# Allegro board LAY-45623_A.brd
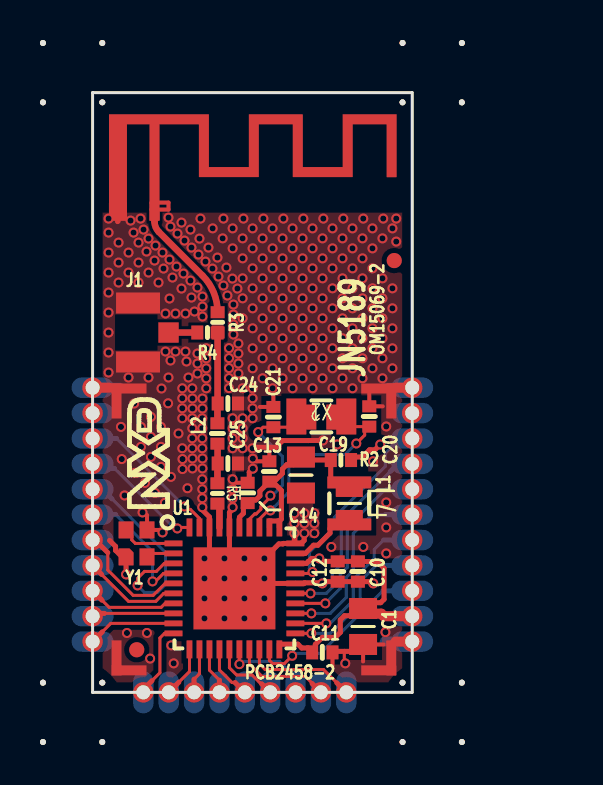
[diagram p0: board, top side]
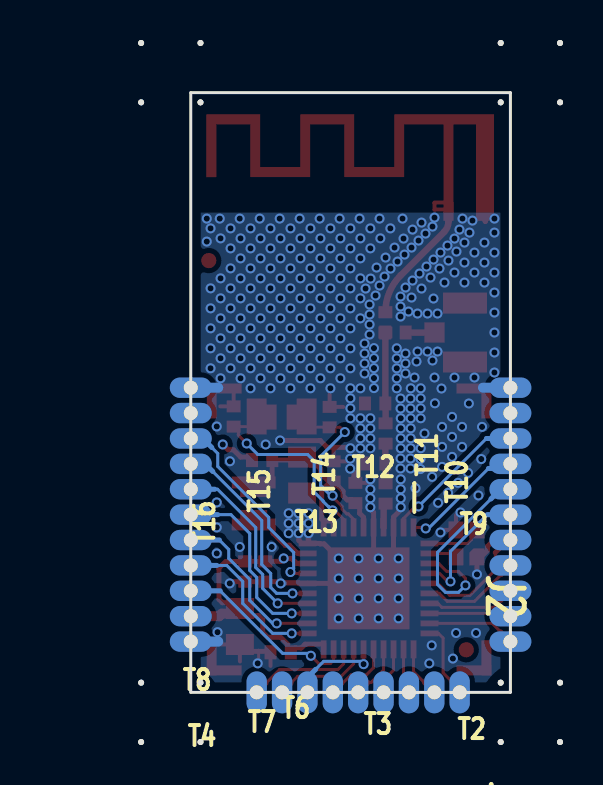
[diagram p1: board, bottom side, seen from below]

Outline 16 x 30 mm; copper layers: TOP, ANALOGUE GROUND, DIGITAL GROUND, BOTTOM. Coordinates in mm from the lower left corner of the outline.
Outline path: 0,30 16,30 16,0 0,0 0,30

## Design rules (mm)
net group ALIM: nets N16830755 N16830789 VDD
net group DEFAUT: nets LA LB N16830681 N16830775 N16832469 N16842652 PIO_0/SPI1_SCK PIO_1/SPI1_MISO PIO_2/SPI1_MOSI PIO_3/SPI1_SSELN0 PIO_4/PWM4-PU PIO_5/ISP_ENTRY PIO_6/PWM6-PD PIO_7/PWM7-PD PIO_8/USART0_TXD PIO_9/USART0_RXD PIO_10/I2C0_SCL PIO_11/I2C0_SDA PIO_12/SWCLK PIO_13/SWDIO PIO_14/ADC0 PIO_15/ADC1 PIO_16/SPIFI_CSN PIO_17/SPIFI_IO3 PIO_18/SPIFI_CLK PIO_19/SPIFI_IO0 PIO_20/SPIFI_IO2 PIO_21_SPIFI_IO1 RSTN
net group Z50: nets N16830709 N16830719 N16830729 N16849423 N16850832

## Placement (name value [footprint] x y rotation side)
1  BUBBLE-01  [BUBBLE_DIAM8]  23.55 23.95 0 top
ANT1  NC  [PCB_ANT_APPS]  3.1 23.85 0 top
C1  10uF  [C0805]  13.54 3.29 90 top
C10  100nF  [C0402]  13.28 6.04 90 top
C11  100nF  [C0402]  11.5 2 0 top
C12  47pF  [C0402]  12.27 6.04 90 top
C13  100nF  [C0402]  8.85 11.05 90 top
C14  47pF  [C0402]  7.76 9.97 90 top
C19  10uF  [C0805]  10.43 10.87 270 top
C20  NC  [C0402]  13.85 13.8 270 top
C21  NC  [C0402]  9.05 13.77 90 top
C24  0.8pF  [C0402]  6.77 14.45 180 top
C25  2.0pF  [C0402]  6.77 11.45 180 top
FID1  NC  [FID1]  2.21 2.13 0 top
FID2  NC  [FID1]  15.1 21.6 0 top
J1  SMC_UFL  [SMC-UFL-R-SMT]  2.27 18 270 top
L1  4,7uH_NC  [IND_CB_2518_2520]  12.85 9.45 270 top
L2  2.9nH  [SELF_0402]  6.25 12.95 270 top
L4  4.7uH  [0805C_IPCC]  12.85 9.45 270 top
LY1  NC  [LYRE_31PTS_CARRIER]  0 12.7 0 top
NOREF  -  []  16 0 90 top
NOREF#2  -  []  2.8 11.95 90 top
NOREF#3  -  [unnamed#2]  17 -1 0 top
NOREF#4  -  []  0 30 0 top
NOREF#5  -  [unnamed#2]  -1 31 0 top
NOREF#6  -  [unnamed#2]  17 31 0 top
NOREF#7  -  []  0 0 0 top
NOREF#8  -  [unnamed#2]  -1 -1 0 top
NOREF#9  -  []  0 0 90 top
NOREF#10  -  []  62.65 28.15 0 top
NOREF#11  -  []  16.52 -165.47 0 top
NOREF#12  -  []  -76.6 -194.1 0 top
R2  NC  [R0402]  12.43 11.62 0 top
R3  0R  [R0402]  6.26 18.51 270 top
R4  NC  [R0402]  5.75 18 180 top
R5  0R  [R0402]  6.25 9.95 270 top
SH1  SHIELD-13.7X14.1  [SHIELD_13MM7X14MM1]  1.2 1.1 0 top
U1  JN5189_40  [SOT618-1_HVQFN40_050_JN518X]  7.1 5.2 0 top
X1  32.768Khz_NC  [NX3215SA]  11.45 13.8 180 top
X2  32.768Khz  [NX2012SA]  11.45 13.77 180 top
Y1  32.000Mhz  [NX2016SA]  2.2 7.45 270 top

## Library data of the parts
1 = BUBBLE: alternate symbols: (BUBBLE_DIAM4)
ANT1 = ANTENNA_JN518x: alternate symbols: (pcb_ant_apps_flip)
C1 C19 = CAPA: alternate symbols: (0805C); tolerance: 10%
C10-C14 = CAPA: User Part Number: BCNNUMBER; Tolerance: 5%; alternate symbols: (0402C); tolerance: 5%
C20 C21 = CAPA: User Part Number: BCNNUMBER; Tolerance: -; alternate symbols: (0402C); tolerance: -
C24 C25 = CAPA: User Part Number: BCNNUMBER; Tolerance: +/-0.1pF; alternate symbols: (0402C); tolerance: +/-0.1pF
FID1 FID2 = MIRE
J1 = SMC_UFL
L1 = SELF: Tolerance: TOLERANCE; User Part Number: PARTNUM
L2 = SELF: Tolerance: TOLERANCE; User Part Number: BCNNUMBER
L4 = SELF
LY1 = LYRE_MODJN518x_31PTS
R2 R4 = RES: User Part Number: BCNNUMBER; Tolerance: -; tolerance: -
R3 R5 = RES: User Part Number: BCNNUMBER; Tolerance: -; alternate symbols: (0402R); tolerance: -
SH1 = SHIELD_8PTS
U1 = JN518x_QFN40: Tolerance: TOL; User Part Number: PN
X1 X2 = XTAL
Y1 = XTAL_NX2016_4P

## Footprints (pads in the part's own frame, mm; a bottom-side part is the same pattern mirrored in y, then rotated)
0805C_IPCC
  rect 0.95x1.35 smd: 1(-0.8,0) 2(0.8,0)
BUBBLE_DIAM8
  round 0 smd: 1(0,0)
C0402
  rect 0.6x0.7 smd: 1(-0.508,0) 2(0.508,0)
C0805
  rect 1.05x1.4 smd: 1(-0.9,0) 2(0.9,0)
FID1
  round 0.76 smd: 1(0,0)
IND_CB_2518_2520
  rect 0.6x2.2 smd: 1(-1.05,0) 2(1.05,0)
LYRE_31PTS_CARRIER
  round 1.02 hole 0.7: 1(0,2.54) 2(0,1.27) 3(0,0) 4(0,-1.27) 5(0,-2.54) 6(0,-3.81) 7(0,-5.08) 8(0,-6.35) 9(0,-7.62) 10(0,-8.89) 11(0,-10.16) 12(2.54,-12.7) 13(3.81,-12.7) 14(5.08,-12.7) 15(6.35,-12.7) 16(7.62,-12.7) 17(8.89,-12.7) 18(10.16,-12.7) 19(11.43,-12.7) 20(12.7,-12.7) 21(16,-10.16) 22(16,-8.89) 23(16,-7.62) 24(16,-6.35) 25(16,-5.08) 26(16,-3.81) 27(16,-2.54) 28(16,-1.27) 29(16,0) 30(16,1.27) 31(16,2.54)
NX2012SA
  rect 1x1.25 smd: 1(-0.75,0) 2(0.75,0)
NX2016SA
  rect 0.85x0.75 smd: 1(-0.675,-0.525) 3(0.675,0.525) 4(-0.675,0.525)
  custom 0.188x0.188 smd: 2(0.675,-0.525)
NX3215SA
  rect 1x1.8 smd: 1(-1.25,0) 2(1.25,0)
PCB_ANT_APPS
  rect 0.9x0.9 smd: 1(-1.829,0.2)
  rect 0.5x0.5 smd: 3(0,0)
R0402
  rect 0.6x0.7 smd: 1(-0.508,0) 2(0.508,0)
SELF_0402
  rect 0.6x0.7 smd: 1(-0.508,0) 2(0.508,0)
SHIELD_13MM7X14MM1
  rect 0.5x1.75 smd: 1(0,0.625) 4(13.75,0.625) 5(13.75,13.475) 8(0,13.475)
  rect 1.75x0.5 smd: 2(0.625,0) 3(13.125,0) 6(13.125,14.1) 7(0.625,14.1)
SMC-UFL-R-SMT
  rect 1.016x1.016 smd: 1(0,1.525)
  rect 1.05x2.2 smd: 2(-1.475,0) 3(1.475,0)
SOT618-1_HVQFN40_050_JN518X
  rect 0.9x0.29 smd: 1(-3.05,2.25) 2(-3.05,1.75) 3(-3.05,1.25) 4(-3.05,0.75) 5(-3.05,0.25) 6(-3.05,-0.25) 7(-3.05,-0.75) 8(-3.05,-1.25) 9(-3.05,-1.75) 10(-3.05,-2.25) 21(3.05,-2.25) 22(3.05,-1.75) 23(3.05,-1.25) 24(3.05,-0.75) 25(3.05,-0.25) 26(3.05,0.25) 27(3.05,0.75) 28(3.05,1.25) 29(3.05,1.75) 30(3.05,2.25)
  rect 0.29x0.9 smd: 11(-2.25,-3.05) 12(-1.75,-3.05) 13(-1.25,-3.05) 14(-0.75,-3.05) 15(-0.25,-3.05) 16(0.25,-3.05) 17(0.75,-3.05) 18(1.25,-3.05) 19(1.75,-3.05) 20(2.25,-3.05) 31(2.25,3.05) 32(1.75,3.05) 33(1.25,3.05) 34(0.75,3.05) 35(0.25,3.05) 36(-0.25,3.05) 37(-0.75,3.05) 38(-1.25,3.05) 39(-1.75,3.05) 40(-2.25,3.05)
  rect 4.1x4.1 smd: 41(0,0)
unnamed#2
  round 0.3 hole 0.4 unplated: (-1.485,1.485) (-1.485,-1.485) (1.485,1.485) (1.485,-1.485)

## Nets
GND: ANT1.1(GND) C1.1 C10.1 C11.2 C12.1 C13.2 C14.2 C19.2 C20.1 C21.2 C24.1 C25.1 J1.2 J1.3 LY1.1(GND(1)) LY1.21(GND(2)) LY1.31(GND(3)) SH1.1(GND#1) SH1.2(GND#2) SH1.3(GND#3) SH1.4(GND#4) SH1.5(GND#5) SH1.6(GND#6) SH1.7(GND#7) SH1.8(GND#8) U1.26(TRST) U1.30(VSS_DCDC) U1.36(VSS_RF(1)) U1.38(VSS_RF(2)) U1.41(VSS (EXPOSED DIE PAD)) Y1.2 Y1.4
VDD: C1.2 C10.2 C11.1 C12.2 LY1.22(VDD) R2.2 U1.20(VDDE) U1.28(VBAT)
LA: LY1.4(LA) U1.40(LA/NC)
LB: LY1.3(LB) U1.39(LB/NC)
PIO_0/SPI1_SCK: LY1.5(PIO0) U1.3(PIO0)
PIO_1/SPI1_MISO: LY1.6(PIO1) U1.4(PIO1)
PIO_2/SPI1_MOSI: LY1.7(PIO2) U1.5(PIO2)
PIO_3/SPI1_SSELN0: LY1.8(PIO3) U1.6(PIO3)
PIO_4/PWM4-PU: LY1.9(PIO4) U1.7(PIO4)
PIO_5/ISP_ENTRY: LY1.10(PIO5/ISP_ENTRY) U1.8(PIO5/ISP_ENTRY)
PIO_6/PWM6-PD: LY1.11(PIO6) U1.9(PIO6)
PIO_7/PWM7-PD: LY1.12(PIO7) U1.10(PIO7)
PIO_8/USART0_TXD: LY1.13(PIO8/TXD0) U1.11(PIO8/TXD0)
PIO_9/USART0_RXD: LY1.14(PIO9/RXD0) U1.12(PIO9/RXD0)
PIO_10/I2C0_SCL: LY1.15(PIO10) U1.13(PIO10)
PIO_11/I2C0_SDA: LY1.16(PIO11) U1.14(PIO11)
PIO_12/SWCLK: LY1.17(PIO12/SWCLK) U1.15(PIO12/SWCLK)
PIO_13/SWDIO: LY1.18(PIO13/SWDIO) U1.16(PIO13/SWDIO)
PIO_14/ADC0: LY1.19(PIO14/ADC0) U1.17(PIO14/ADC0)
PIO_15/ADC1: LY1.20(PIO15/ADC1) U1.18(PIO15/ADC1)
PIO_16/SPIFI_CSN: LY1.23(PIO16/ADC2) U1.19(PIO16/ADC2)
PIO_17/SPIFI_IO3: LY1.24(PIO17/ADC3) U1.21(PIO17/ADC3)
PIO_18/SPIFI_CLK: LY1.25(PIO18/ADC4) U1.22(PIO18/ADC4)
PIO_19/SPIFI_IO0: LY1.26(PIO19/ADC5) U1.23(PIO19/ADC5)
PIO_20/SPIFI_IO2: LY1.27(PIO20/ACP) U1.24(PIO20/ACP)
PIO_21_SPIFI_IO1: LY1.28(PIO21/ACM) U1.25(PIO21/ACM)
RSTN: LY1.29(RSTN) U1.27(RSTN)
N16830681: U1.1(XTAL_P) Y1.1
N16830709: C24.2 L2.1 R3.2 R4.1
N16830719: C25.2 L2.2 R5.1
N16830729: R5.2 U1.37(RF_IO)
N16830755: C13.1 C14.1 C19.1 L1.1 L4.1 R2.1 U1.31(FB) U1.32(VDD_PMU) U1.35(VDD_RADIO)
N16830775: C20.2 U1.33(XTAL_32K_P) X1.1 X2.1
N16830789: L1.2 L4.2 U1.29(LX)
N16832469: C21.1 U1.34(XTAL_32K_N) X1.2 X2.2
N16842652: U1.2(XTAL_N) Y1.3
N16849423: J1.1 R4.2
N16850832: ANT1.3(IN) R3.1

Pads without a net: 1 1; FID1 1; FID2 1; LY1 2 30

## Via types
v1: diameter 0.5, hole 0.31, TOP to BOTTOM, 370 vias

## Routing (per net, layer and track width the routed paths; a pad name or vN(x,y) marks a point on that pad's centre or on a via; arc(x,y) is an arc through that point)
GND: length 43
  TOP w0.15: v1(12.65,1.45) 12.6,1.5 12.6,2.05
  TOP w0.2: 3.43,8.12 Y1.4 2.73,8.88 ; 13.85,14.93 C20.1 14.53,14.31 ; 14.57,2.4 C1.1 13.54,1.54 ; 7.08,10.48 C14.2 ; U1.30 10.15,7.92 ; 9.05,14.9 C21.2 8.37,14.28 ; 8.85,12.18 C13.2 8.17,11.56 ; 12.01,1.32 C11.2
  TOP w0.25: 8.85,6.95 9.32,7.42 9.53,7.42 9.55,7.45 10.1,7.45 ; 0.85,7.6 1.15,7.3 1.15,7.1 1.48,6.78 Y1.2 v1(1.68,5.9) ; v1(14.05,5.45) 13.96,5.54 C10.1 C12.1 11.59,5.54 v1(11.5,5.45) ; v1(7.01,9.26) 7.01,9.16 6.85,9 U1.36 6.85,6.95 ; 8.85,5.45 U1.26 10.59,5.45 10.62,5.48 11.47,5.48 v1(11.5,5.45) ; v1(10.6,7.96) 10.59,7.95 10.59,7.6 10.44,7.45 U1.30 10.1,7.45 ; v1(11.5,5.45) 11.54,5.41 ; 10.1,7.45 v1(10.1,7.96) ; v1(8.02,11.19) 7.84,11.01 7.84,10.54 7.76,10.46 ; v1(8.01,12.21) 8.06,12.26 9.18,12.26 9.52,12.6 10.81,12.6 10.82,12.6 v1(11.53,12.6) ; 1.25,23.55 1.27,23.57 ANT1.1 ; v1(5.49,9.26) 5.49,9.13 5.85,8.77 U1.38 5.85,6.95 ; C11.2 12.06,2.05 13.05,2.05 13.27,2.27 13.59,2.27
  TOP w0.5: LY1.21 15.16,2.54 ; LY1.1 0.84,15.24 ; 15.16,15.24 LY1.31
  ANALOGUE GROUND w0.5: 15.21,15.24 LY1.31 ; 15.21,2.54 LY1.21 ; LY1.1 0.79,15.24
  DIGITAL GROUND w0.5: LY1.1 0.79,15.24 ; 15.21,2.54 LY1.21 ; 15.21,15.24 LY1.31
  BOTTOM w0.5: 14.62,2.54 LY1.21 ; LY1.1 1.38,15.24 ; 14.62,15.24 LY1.31
  vias: v1(0.8,23.7) v1(0.8,23) v1(0.8,22) v1(0.8,21) v1(0.8,20) v1(0.8,19) v1(0.8,18) v1(0.8,17) v1(0.8,16) v1(1.3,22.5) v1(1.3,21.5) v1(1.3,20.5) v1(1.42,13.28) v1(1.46,11.67) v1(1.6,9.85) v1(1.72,2.97) v1(1.8,22) v1(1.8,21) v1(1.8,15.75) v1(1.9,23.6) v1(2.05,23) v1(2.08,14.45) v1(2.12,10.98) v1(2.3,22.5) v1(2.3,21.5) v1(2.3,20.5) v1(2.4,23.7) v1(2.42,13.28) v1(2.42,12.28) v1(2.55,23.15) v1(2.5,9) v1(2.62,10.48) v1(2.7,22.05) v1(2.72,2.97) v1(2.8,22.7) v1(2.8,21) v1(2.8,15.75) v1(2.92,13.78) v1(2.92,12.78) v1(2.92,11.78) v1(2.88,1.69) v1(3.15,22.35) v1(3.1,21.6) v1(3.12,9.98) v1(3.3,20.5) v1(3.42,13.28) v1(3.42,12.28) v1(3.42,11.28) v1(3.5,22) v1(3.55,21.2) v1(3.45,15.2) v1(3.5,8) v1(3.65,18.95) v1(3.65,17.05) v1(3.62,9.48) v1(3.8,23.75) v1(3.8,15.75) v1(3.78,14.46) v1(3.9,23.3) v1(3.85,21.65) v1(3.85,19.7) v1(3.9,16.6) v1(3.92,10.78) v1(3.94,2.35) v1(4,20.75) v1(4.06,1.45) v1(4.25,22.95) v1(4.2,21.3) v1(4.15,18.95) v1(4.15,17.05) v1(4.3,12.95) v1(4.45,23.5) v1(4.55,20.95) v1(4.45,20.2) v1(4.49,15.21) v1(4.49,14.71) v1(4.49,14.21) v1(4.49,13.71) v1(4.49,12.21) v1(4.5,11.67) v1(4.5,11.17) v1(4.6,22.6) v1(4.65,18.95) v1(4.65,17.05) v1(4.7,16.55) v1(4.8,15.75) v1(4.75,10.21) v1(4.9,23.15) v1(4.9,20.6) v1(4.95,22.25) v1(4.95,19.75) v1(4.99,15.21) v1(5,14.7) v1(5,14.2) v1(4.99,13.71) v1(4.99,13.21) v1(4.99,12.71) v1(4.99,12.21) v1(5,11.7) v1(5,11.2) v1(5.1,19.05) v1(5.25,20.25) v1(5.25,16.95) v1(5.25,16.45) v1(5.25,15.95) v1(5.35,22.7) v1(5.3,21.9) v1(5.4,23.7) v1(5.5,19.8) v1(5.5,19.3) v1(5.5,18.8) v1(5.5,14.7) v1(5.5,14.2) v1(5.49,13.71) v1(5.49,13.21) v1(5.49,12.71) v1(5.49,12.21) v1(5.5,11.7) v1(5.5,11.2) v1(5.49,10.66) v1(5.49,10.16) v1(5.49,9.71) v1(5.6,6.7) v1(5.6,5.7) v1(5.6,4.7) v1(5.6,3.7) v1(5.65,21.55) v1(5.69,17.21) v1(5.69,16.71) v1(5.69,16.21) v1(5.69,15.71) v1(5.69,15.21) v1(5.8,22.25) v1(6.01,23.21) v1(6,21.2) v1(6.25,21.75) v1(6.3,20.8) v1(6.55,23.7) v1(6.51,22.71) v1(6.55,20.35) v1(6.6,6.7) v1(6.6,5.7) v1(6.6,4.7) v1(6.6,3.7) v1(6.7,21.25) v1(6.75,19.85) v1(6.83,17.22) v1(6.83,16.72) v1(6.83,16.22) v1(6.83,15.72) v1(6.83,15.22) v1(7.01,23.21) v1(7.01,22.21) v1(7,20.7) v1(7.05,19.4) v1(7.05,18.9) v1(7.05,18.4) v1(7.05,17.9) v1(7.01,13.71) v1(7.01,13.21) v1(7.01,12.71) v1(7.01,12.21) v1(7.01,10.66) v1(7.01,10.16) v1(7.01,9.71) v1(7.25,20.2) v1(7.3,17.45) v1(7.3,16.95) v1(7.3,16.45) v1(7.3,15.95) v1(7.55,23.7) v1(7.51,22.71) v1(7.51,21.71) v1(7.51,20.71) v1(7.51,19.71) v1(7.51,18.71) v1(7.51,15.21) v1(7.51,13.71) v1(7.51,13.21) v1(7.51,12.71) v1(7.51,12.21) v1(7.6,6.7) v1(7.6,5.7) v1(7.6,4.7) v1(7.6,3.7) v1(8.01,23.21) v1(8.01,22.21) v1(8.01,21.21) v1(8.01,20.21) v1(8.01,19.21) v1(8.01,18.21) v1(8.01,17.21) v1(8.01,16.21) v1(8.01,15.21) v1(8.01,14.71) v1(8.01,14.21) v1(8.01,13.71) v1(8.02,11.69) v1(8.51,22.71) v1(8.51,21.71) v1(8.51,20.71) v1(8.51,19.71) v1(8.51,18.71) v1(8.51,17.71) v1(8.51,16.71) v1(8.51,15.71) v1(8.55,23.7) v1(8.6,6.7) v1(8.6,5.7) v1(8.6,4.7) v1(8.6,3.7) v1(9.01,23.21) v1(9.01,22.21) v1(9.01,21.21) v1(9.01,20.21) v1(9.01,19.21) v1(9.01,18.21) v1(9.01,17.21) v1(9.01,16.21) v1(9.01,15.21) v1(9.51,22.71) v1(9.51,21.71) v1(9.51,20.71) v1(9.51,19.71) v1(9.51,18.71) v1(9.51,17.71) v1(9.51,16.71) v1(9.51,15.71) v1(9.55,23.7) v1(10.01,23.21) v1(10.01,22.21) v1(10.01,21.21) v1(10.01,20.21) v1(10.01,19.21) v1(10.01,18.21) v1(10.01,17.21) v1(10.01,16.21) v1(10.01,15.21) v1(10.1,8.96) v1(10.1,8.46) v1(10.51,22.71) v1(10.51,21.71) v1(10.51,20.71) v1(10.51,19.71) v1(10.51,18.71) v1(10.51,17.71) v1(10.51,16.71) v1(10.51,15.71) v1(10.55,23.7) v1(10.6,8.96) v1(10.6,8.46) v1(11.01,23.21) v1(11.01,22.21) v1(11.01,21.21) v1(11.01,20.21) v1(11.01,19.21) v1(11.01,18.21) v1(11.01,17.21) v1(11.01,16.21) v1(11.01,15.21) v1(11.1,8.96) v1(11.1,8.46) v1(11.1,7.96) v1(11.51,22.71) v1(11.51,21.71) v1(11.51,20.71) v1(11.51,19.71) v1(11.51,18.71) v1(11.51,17.71) v1(11.51,16.71) v1(11.51,15.71) v1(11.55,23.7) v1(11.95,7.28) v1(12.01,23.21) v1(12.01,22.21) v1(12.01,21.21) v1(12.01,20.21) v1(12.01,19.21) v1(12.01,18.21) v1(12.01,17.21) v1(12.01,16.21) v1(12.01,15.21) v1(12.25,12.4) v1(12.51,22.71) v1(12.51,21.71) v1(12.51,20.71) v1(12.51,19.71) v1(12.51,18.71) v1(12.51,17.71) v1(12.51,16.71) v1(12.51,15.71) v1(12.55,23.7) v1(13.01,23.21) v1(13.01,22.21) v1(13.01,21.21) v1(13.01,20.21) v1(13.01,19.21) v1(13.01,18.21) v1(13.01,17.21) v1(13.01,16.21) v1(13.01,15.21) v1(13.51,22.71) v1(13.51,21.71) v1(13.51,20.71) v1(13.51,19.71) v1(13.51,18.71) v1(13.51,17.71) v1(13.51,16.71) v1(13.51,15.71) v1(13.55,23.7) v1(13.55,7.28) v1(14.01,23.21) v1(14.01,22.21) v1(14.01,21.21) v1(14.01,20.21) v1(14.01,19.21) v1(14.01,18.21) v1(14.01,17.21) v1(14.01,16.21) v1(14.04,11.56) v1(14.51,22.71) v1(14.51,20.71) v1(14.51,19.71) v1(14.51,18.71) v1(14.51,17.71) v1(14.51,16.71) v1(14.51,15.71) v1(14.55,23.7) v1(14.7,13.3) v1(14.7,9.5) v1(14.7,8.25) v1(14.7,6.95) v1(14.66,3.01) v1(15.01,23.21) v1(15.01,20.21) v1(15.01,19.21) v1(15.01,18.21) v1(15.01,17.21) v1(15.01,16.21) v1(15.2,23.7) v1(15.2,22.55)
VDD: length 29.2
  TOP w0.25: R2.2 13.09,11.77 13.5,11.77 13.86,12.13 14.13,12.13 v1(14.4,12.4) ; 13.88,4.49 13.83,4.49 C1.2 ; 13.88,4.49 14.42,4.49 14.59,4.66 14.59,6.21 14.25,6.54 13.29,6.54 C10.2 C12.2 11.5,6.55 v1(11.35,6.7) 10.97,6.7 10.82,6.55 10.8,6.55 10.7,6.45 U1.28 ; 13.88,4.49 13.59,4.2 C1.2 ; C1.2 13.36,4.2 13,3.83 12.61,3.83 12.4,3.62 12.4,3 12.15,2.75 11.5,2.75 11.15,2.4 11.15,2.16 C11.1 10.77,2.22 10.47,2.22 10.28,2.41 9.35,2.41 U1.20
  TOP w0.5: 13.8,3.94 14.45,3.94 14.57,3.81 LY1.22 ; 13.8,3.94 13.75,3.94 13.49,4.2 ; 13.8,3.94 C1.2
  DIGITAL GROUND w0.25: v1(11.35,6.7) 11.67,6.38 14.94,6.38 15.27,6.71 15.27,7.19 15.2,7.25 15.2,7.95 15.27,8.01 15.27,8.49 15.2,8.55 15.2,9.2 15.27,9.26 15.27,9.74 15.2,9.8 15.2,11.5 14.4,12.3 v1(14.4,12.4)
LA: length 6.2
  TOP w0.15: v1(4.24,8.2) 4.29,8.25 U1.40
  BOTTOM w0.15: v1(4.24,8.2) 4.1,8.2 1.1,11.2
  BOTTOM w0.25: 1.1,11.2 0.23,11.2 LY1.4
LB: length 7.5
  TOP w0.15: v1(4.6,9.3) 4.75,9.15 4.9,9.15 5.35,8.7 U1.39
  BOTTOM w0.15: 1.2,12.7 v1(4.6,9.3)
  BOTTOM w0.25: LY1.3 1.2,12.7
PIO_0/SPI1_SCK: length 10.7
  TOP w0.15: v1(2.25,5.35) 2.25,5.7 2.6,6.05 3.19,6.05 3.59,6.45 U1.3
  BOTTOM w0.15: 0.97,9.68 3.65,7 3.65,5.4 3.25,5 2.6,5 v1(2.25,5.35)
  BOTTOM w0.25: 0.97,9.68 0.49,10.16 LY1.5
PIO_1/SPI1_MISO: length 6.5
  TOP w0.15: U1.4 3.55,5.95 3.15,5.55 v1(3,5.55)
  BOTTOM w0.15: 1.16,8.89 3,7.05 v1(3,5.55)
  BOTTOM w0.25: LY1.6 1.16,8.89
PIO_2/SPI1_MOSI: length 6
  TOP w0.15: U1.5 3.63,5.45 3.03,4.85 2.03,4.85 0.76,6.12 0.76,6.99
  TOP w0.25: LY1.7 0.13,7.62 0.76,6.99
PIO_3/SPI1_SSELN0: length 5
  TOP w0.15: U1.6 3.56,4.95 3.16,4.55 1.8,4.55 0.45,5.9
  TOP w0.25: 0.45,5.9 LY1.8
PIO_4/PWM4-PU: length 4.5
  TOP w0.15: 0.47,4.61 0.83,4.25 3.43,4.25 3.63,4.45 U1.7
  TOP w0.25: 0.47,4.61 LY1.9
PIO_5/ISP_ENTRY: length 4.1
  TOP w0.15: U1.8 0.59,3.95
  TOP w0.25: 0.59,3.95 0.14,3.95 LY1.10
PIO_6/PWM6-PD: length 4.4
  TOP w0.15: U1.9 0.91,3.45 0.48,3.02
  TOP w0.25: 0.48,3.02 LY1.11
PIO_7/PWM7-PD: length 3.8
  TOP w0.15: U1.10 3.6,2.95 3.37,2.72 3.37,0.98 2.97,0.58
  TOP w0.25: 2.97,0.58 2.54,0.15 LY1.12
PIO_8/USART0_TXD: length 2.6
  TOP w0.15: U1.11 4.85,1.04 4.32,0.51
  TOP w0.25: 4.32,0.51 LY1.13
PIO_9/USART0_RXD: length 2.3
  TOP w0.15: 5.08,0.66 5.35,0.93 U1.12
  TOP w0.25: 5.08,0.66 LY1.14
PIO_10/I2C0_SCL: length 2.4
  TOP w0.15: U1.13 5.85,1.11 6.35,0.61
  TOP w0.25: 6.35,0.61 LY1.15
PIO_11/I2C0_SDA: length 2.8
  TOP w0.15: 7.13,0.49 6.98,0.49 6.35,1.12 U1.14
  TOP w0.25: 7.13,0.49 LY1.16
PIO_12/SWCLK: length 3.5
  TOP w0.15: 8.46,0.42 8.43,0.42 7.98,0.87 7.21,0.87 6.85,1.23 U1.15
  TOP w0.25: 8.46,0.42 LY1.17
PIO_13/SWDIO: length 4.7
  TOP w0.15: U1.16 v1(7.35,1.41)
  BOTTOM w0.15: 9.75,1.15 9.35,1.55 7.49,1.55 v1(7.35,1.41)
  BOTTOM w0.25: 9.75,1.15 10.16,0.74 LY1.18
PIO_14/ADC0: length 4.9
  TOP w0.15: U1.17 7.85,1.43 8.47,0.8 10.65,0.8 10.99,0.46 10.99,0.44
  TOP w0.25: 10.99,0.44 LY1.19
PIO_15/ADC1: length 5.7
  TOP w0.15: 12.22,0.47 11.56,1.14 8.63,1.14 8.35,1.43 U1.18
  TOP w0.25: 12.22,0.47 LY1.20
PIO_16/SPIFI_CSN: length 9.3
  TOP w0.15: v1(9.99,1.83) 9.6,1.44 9.01,1.44 8.85,1.6 U1.19
  BOTTOM w0.15: v1(9.99,1.83) 10.11,1.95 11.4,1.95 14.53,5.08
  BOTTOM w0.25: LY1.23 14.53,5.08
PIO_17/SPIFI_IO3: length 7.9
  TOP w0.15: U1.21 v1(10.95,2.95)
  BOTTOM w0.15: 14.7,6.35 14.2,6.35 13.4,5.55 13.4,4.45 11.9,2.95 v1(10.95,2.95)
  BOTTOM w0.25: LY1.24 14.7,6.35
PIO_18/SPIFI_CLK: length 8.5
  TOP w0.15: U1.22 v1(11.7,3.45)
  BOTTOM w0.15: v1(11.7,3.45) 11.9,3.45 13.05,4.6 13.05,5.65 14.1,6.7 14.1,7.15 14.57,7.62
  BOTTOM w0.25: LY1.25 14.57,7.62
PIO_19/SPIFI_IO0: length 9.6
  TOP w0.15: U1.23 v1(10.95,3.95)
  BOTTOM w0.15: 14.65,8.89 13.99,8.89 13.05,7.95 13.05,6.1 12.7,5.75 12.7,4.75 11.9,3.95 v1(10.95,3.95)
  BOTTOM w0.25: 14.65,8.89 LY1.26
PIO_20/SPIFI_IO2: length 9.8
  TOP w0.15: v1(11.65,4.45) U1.24
  BOTTOM w0.15: 14.8,10.16 14.66,10.16 12.75,8.25 12.75,6.25 12.4,5.9 12.4,5.2 v1(11.65,4.45)
  BOTTOM w0.25: 14.8,10.16 LY1.27
PIO_21_SPIFI_IO1: length 10.2
  TOP w0.15: U1.25 v1(10.91,4.95)
  BOTTOM w0.15: v1(10.91,4.95) 11.7,4.95 12,5.25 12,5.95 12.45,6.4 12.45,8.6 14.9,11.05
  BOTTOM w0.25: LY1.28 15.28,11.43 14.9,11.05
RSTN: length 10.1
  TOP w0.15: U1.27 10.94,5.95 v1(11.01,6.02)
  BOTTOM w0.15: 14.95,12.25 14.65,11.95 14.65,11.3 12.1,8.75 12.1,8.25 10.85,7 10.85,6.18 v1(11.01,6.02)
  BOTTOM w0.25: 14.95,12.25 15.4,12.7 LY1.29
N16830681: length 2.8
  TOP w0.15: U1.1 2.14,7.45 1.96,7.63 1.96,7.84 Y1.1
N16830709: length 4.6
  TOP w0.33: 6.25,14.44 L2.1 ; 6.25,14.44 C24.2 ; 6.25,14.44 6.25,14.44 6.26,14.45 R4.1
N16830719: length 2
  TOP w0.33: 6.26,11.45 C25.2 ; 6.26,11.45 6.26,11.45 6.25,11.44 R5.1 ; 6.26,11.45 6.26,12.43 L2.2
N16830729: length 1.2
  TOP w0.33: U1.37 6.35,9.34 R5.2
N16830755: length 12.1
  TOP w0.25: U1.35 7.35,8.76 7.55,8.96 7.55,9.26 7.91,9.62 8.17,9.62 8.38,9.83 8.38,10.07 C13.1 9.01,10.54 ; 9.35,8.57 U1.31 ; 9.35,8.57 8.85,8.57 U1.32 ; 9.35,8.57 9.45,8.67 9.45,10.1 9.01,10.54 ; 9.01,10.54 9.09,10.54 9.5,10.95 9.5,11.17 9.72,11.39 10.05,11.39 C19.1 10.58,11.62 R2.1 11.92,10.68 12.1,10.5 L1.1
N16830775: length 10.3
  TOP w0.15: U1.33 8.35,8.66 8.79,9.1 v1(8.9,9.1) ; X1.1 12.7,13.7 13.11,13.29 C20.2 13.62,13.06 13.62,12.87 v1(13.2,12.45)
  BOTTOM w0.15: v1(13.2,12.45) 12.65,11.9 10.15,11.9 9.82,11.57 9.82,10.03 9.38,9.57 9.38,9.55 9.1,9.28 9.07,9.28 v1(8.9,9.1)
N16830789: length 3.4
  TOP w0.25: L1.2 12.1,8.4 11.88,8.18 11.88,7.96 11.28,7.36 11.06,7.36 10.65,6.95 U1.29
N16832469: length 8.3
  TOP w0.15: U1.34 7.85,8.66 8.11,8.93 8.19,8.93 8.43,9.16 8.43,9.3 8.9,9.77 v1(8.9,9.84) ; X1.2 10.2,13.7 9.76,13.26 C21.1 8.53,13.26 v1(8.29,13.02)
  BOTTOM w0.15: v1(8.29,13.02) 9.5,11.81 9.5,10.35 8.99,9.84 v1(8.9,9.84)
N16842652: length 1.4
  TOP w0.15: U1.2 2.9,6.95 Y1.3
N16849423: length 1.4
  TOP w0.33: R4.2 J1.1
N16850832: length 6
  TOP w0.33: ANT1.3 3.1,23.55 arc(3.16,23.27) 3.31,23.04 5.5,20.85 arc(6.06,20.01) R3.1

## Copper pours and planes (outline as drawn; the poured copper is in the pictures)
GND on TOP (solid shape): 5.82,26.28 7.82,26.28 7.82,28.92 10.52,28.92 10.52,26.28 12.52,26.28 12.52,28.92 15.22,28.92 15.22,25.77 14.72,25.77 14.72,28.42 13.02,28.42 13.02,25.78 10.02,25.78 10.02,28.42 8.32,28.42 8.32,25.78 5.32,25.78 5.32,28.42 3.35,28.42 3.35,23.6 2.85,23.6 2.85,28.42 1.72,28.42 1.72,23.6 0.82,23.6 0.82,28.92 5.82,28.92
GND on TOP: 2,0.5 0.5,0.5 0.5,2.05 0.5,13.2 0.5,24 15.5,24 15.5,13.2 15.5,6.7 14.6,6.7 14.6,4.2 15.5,4.2 15.5,2.05 15.5,0.5 13.2,0.5 ; 20 cut-outs
GND on BOTTOM, ANALOGUE GROUND, DIGITAL GROUND: 2,0.5 0.5,0.5 0.5,2.05 0.5,13.2 0.5,24 15.5,24 15.5,13.2 15.5,2.05 15.5,0.5 13.2,0.5

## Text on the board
Ref Des/Silkscreen Bottom: T9 | T2 | T3 | T12 | T13 | T6 | T7 | T4 | T5 | T8 | T10 | T11 | T14 | T15 | T16 | J1 | J2
Ref Des/Silkscreen Top: PCB2458-2 | OM15069-2 | JN5189
DEVICE_TYPE_TOP: TITRE | TITLE | . | No EVOL | DESSINE/DRAWN | ASCO-SR | REV. | Nbr/Qty | DATE | 22-12-2017 | EVOLUTION/CHANGE | M.BAUDRY | VERIFIE/CHECKED | NUMERO DOCUMENT/DOCUMENT NUMBER | DESS./DRAWN | APPROUVE/APPROVED | ..-..-.... | VERIF./CHECKED | PAGE | BP 2000 - COLOMBELLES | 14906 CAEN CEDEX 9 | 2 Esplanade Anton Philips | SEMICONDUCTORS | JN518x ANTENNA MODULE - OM15069-2 | / | PCB2458-2 | 00
DISPLAY_TOP: 1 | 4 | TOP LAYER | 311
DIMENSION: 4 | BOTTOM LAYER | 311
COMPVAL_TYPE_TOP: 2 | 4 | LAYER 2 | 311
TOLERANCE_TOP: 3 | 4 | LAYER 3 | 311
User.18: 1 | SILKSCREEN TOP | 380
User.19: 2 | SOLDERMASK BOT | 312
User.20: 4 | PASTEMASK BOT | 435
User.22: 1 | PASTEMASK TOP | 435
User.24: 1 | 2 | SOLDERMASK TOP | 312
User.25: 1 | MILLING | 313
User.45: All rights are reserved. Reproduction in | whole or in part is prohibited without | the written consent of the copyright owner | NXP Semiconductors | 2,Esplanade Anton Philips | Campus Effiscience Colombelles | BP 2000 - 14906 CAEN CEDEX 9 | Date | Draw by | Verify | Modifications | SIZE | REV. | IND. | PL. | Date : 22/12/2017 | Draw by : SR-ASCO | Checked by:M.BAUDRY | Project : JN518x | Finition : .... | Material : .... | Protection : .... | Marging : +/-0.1 | Manufact.level : . | Scale : 3/1 | Nbr of layers : . | Silkscreen | TOP   :... | BOTTOM:... | 1 | <- VIA | FIGURE | DIAMETRE / HOLESIZE | 0,30 mm (PERCE) | 0,70 mm +0,10 -0,05 | 0,40 mm +0,10 -0,10 | LEGENDE DE PERCAGE / DRILL LEGEND | ALL UNITS ARE IN MILLIMETERS | PLATED | NON-PLATED | Qte / Qty | 370 | 31 | 16 | ASSEMBLY DRAWING TOP OM15069-2 | JN518x ANTENNA MODULE | D | C | B | A | 4 | 3 | 2 | A4 | PCB2458-2-400 | 00 | File. | TOP/BOTTOM
